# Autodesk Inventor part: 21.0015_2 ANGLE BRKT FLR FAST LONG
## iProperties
Created: 2012-08
Part Number: 21.0015_2 ANGLE BRKT FLR FAST LONG
Document SubType Name: Modeling
Designer: Administrator
Density: 7.85 g/cm^3
Material: Steel
Mass: 757.144 g
Surface Area: 304.184 cm^2
Volume: 96.4515 cm^3
Translation Standard: STEP AP214IS
FileName: 21_0015_0_1.stp
PreProcessor: ACIS
PostProcessor: Build: 236a, Release: 2009 RTM - Date: Fri 02/22/2008
Sent Units: MM
Uncertainty: 1e-06
Author: Administrator
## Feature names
1. Base1
